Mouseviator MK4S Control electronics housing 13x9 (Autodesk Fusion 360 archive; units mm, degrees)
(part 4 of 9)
sketch "Sketch3" plane through (0, 61.9879, 0) normal (0, 1, 0) x axis (-1, 0, 0)
  line L1 (-11.0351, 5.05) -> (-100.8937, 5.05)
  line L2 (-11.0351, 74.95) -> (-11.0351, 5.05)
  line L3 (-100.8937, 74.95) -> (-11.0351, 74.95)
  line L4 (-100.8937, 5.05) -> (-100.8937, 74.95)
  line L5 (-55.9644, -6.6527) -> (-55.9644, 156.5527)
  line L6 (83.5909, 40) -> (-105.6612, 40)
  line L7 (-100.8937, 64.95) -> (-100.8937, 74.95)
  line L8 (-94.8937, 74.95) -> (-100.8937, 74.95)
  line L9 (-94.8937, 59.95) -> (-94.8937, 74.95)
  line L10 (-100.8937, 64.95) -> (-94.8937, 59.95)
  line L11 (-100.9437, 64.9735) -> (-106.8437, 60)
  line L12 (-106.8437, 60) -> (-106.8437, 74.9)
  line L13 (-100.8937, 64.9735) -> (-100.9437, 64.9735)
  line L14 (-100.8937, 74.9) -> (-106.8437, 74.9)
  line L15 (-100.8937, 5.1) -> (-106.8437, 5.1)
  line L16 (-106.8437, 20) -> (-106.8437, 5.1)
  line L17 (-100.9437, 15.0265) -> (-106.8437, 20)
  line L18 (-100.8937, 15.0265) -> (-100.9437, 15.0265)
  line L19 (-100.8937, 15.05) -> (-100.8937, 5.05)
  line L20 (-94.8937, 5.05) -> (-100.8937, 5.05)
  line L21 (-94.8937, 20.05) -> (-94.8937, 5.05)
  line L22 (-100.8937, 15.05) -> (-94.8937, 20.05)
  line L23 (-11.0351, 5.1) -> (-5.0851, 5.1)
  line L24 (-5.0851, 20) -> (-5.0851, 5.1)
  line L25 (-10.9851, 15.0265) -> (-5.0851, 20)
  line L26 (-11.0351, 15.0265) -> (-10.9851, 15.0265)
  line L27 (-11.0351, 15.05) -> (-11.0351, 5.05)
  line L28 (-17.0351, 5.05) -> (-11.0351, 5.05)
  line L29 (-17.0351, 20.05) -> (-17.0351, 5.05)
  line L30 (-11.0351, 15.05) -> (-17.0351, 20.05)
  line L31 (-11.0351, 74.9) -> (-5.0851, 74.9)
  line L32 (-5.0851, 60) -> (-5.0851, 74.9)
  line L33 (-11.0351, 64.9735) -> (-10.9851, 64.9735)
  line L34 (-10.9851, 64.9735) -> (-5.0851, 60)
  line L35 (-11.0351, 64.95) -> (-11.0351, 74.95)
  line L36 (-17.0351, 74.95) -> (-11.0351, 74.95)
  line L37 (-17.0351, 59.95) -> (-17.0351, 74.95)
  line L38 (-11.0351, 64.95) -> (-17.0351, 59.95)
  point P17 (-100.8937, 64.9735)
  point P18 (-100.8937, 74.9)
  point P10 (-100.8937, 74.95)
  point P24 (-100.8937, 5.05)
  point P11 (-100.8937, 64.95)
  point P25 (-100.8937, 15.05)
  point P12 (-94.8937, 74.95)
  point P26 (-94.8937, 5.05)
  point P13 (-94.8937, 59.95)
  point P27 (-94.8937, 20.05)
  point P14 (-100.9437, 64.9735)
  point P22 (-100.9437, 15.0265)
  point P15 (-106.8437, 60)
  point P21 (-106.8437, 20)
  point P16 (-106.8437, 74.9)
  point P19 (-106.8437, 5.1)
  point P23 (-100.8937, 15.0265)
  point P20 (-100.8937, 5.1)
  point P42 (-11.0351, 74.95)
  point P43 (-11.0351, 64.95)
  point P44 (-17.0351, 74.95)
  point P45 (-17.0351, 59.95)
  point P40 (-10.9851, 64.9735)
  point P39 (-5.0851, 60)
  point P37 (-5.0851, 74.9)
  point P41 (-11.0351, 64.9735)
  point P38 (-11.0351, 74.9)
  point P28 (-5.0851, 5.1)
  point P29 (-11.0351, 5.1)
  point P30 (-5.0851, 20)
  point P31 (-10.9851, 15.0265)
  point P32 (-11.0351, 15.0265)
  point P33 (-11.0351, 5.05)
  point P34 (-11.0351, 15.05)
  point P35 (-17.0351, 5.05)
  point P36 (-17.0351, 20.05)
  vertical L5
  horizontal L6
  midpoint L3 L5
  midpoint L2 L6
  coincident L7 P17
  coincident L4 P17
  perpendicular L7 L14
  coincident L4 P18
  symmetric L6 P10 P24
  symmetric L6 P11 P25
  symmetric L6 P12 P26
  symmetric L6 P13 P27
  symmetric L6 P14 P22
  symmetric L6 P15 P21
  symmetric L6 P16 P19
  symmetric L6 P17 P23
  symmetric L6 P18 P20
  symmetric L5 P10 P42
  symmetric L5 P11 P43
  symmetric L5 P12 P44
  symmetric L5 P13 P45
  symmetric L5 P14 P40
  symmetric L5 P15 P39
  symmetric L5 P16 P37
  symmetric L5 P17 P41
  symmetric L5 P18 P38
  symmetric L5 P19 P28
  symmetric L5 P20 P29
  symmetric L5 P21 P30
  symmetric L5 P22 P31
  symmetric L5 P23 P32
  symmetric L5 P24 P33
  symmetric L5 P25 P34
  symmetric L5 P26 P35
  symmetric L5 P27 P36
  dimension "d332_1" distance P12 P13 = 15 (= "join_width2")
  dimension "d333_1" distance P10 P12 = 6 (= "join_depth * 2")
  dimension "d334_1" distance P10 P11 = 10 (= "join_width1")
  dimension "d336_1" distance P15 P16 = 14.9 (= "join_width2 - ( 2 * wall_clearance )")
  dimension "d337_1" distance P16 P18 = 5.95 (= "join_depth * 2 - wall_clearance")
  dimension "d338_1" distance P14 P17 = 0.05 (= "wall_clearance")
sketch "Sketch1" plane through (0, 0, 5) normal (0, 0, 1) x axis (-1, 0, 0)
  line L1 (-98.9644, -53.9879) -> (-98.9644, -59.9879)
  line L2 (-92.9644, -53.9879) -> (-98.9644, -53.9879)
  line L3 (-92.9644, -59.9879) -> (-92.9644, -53.9879)
  line L4 (-98.9644, -59.9879) -> (-92.9644, -59.9879)
  line L5 (-12.9644, 60.0121) -> (-12.9644, 66.0121)
  line L6 (-18.9644, 60.0121) -> (-12.9644, 60.0121)
  line L7 (-18.9644, 66.0121) -> (-18.9644, 60.0121)
  line L8 (-12.9644, 66.0121) -> (-18.9644, 66.0121)
  line L9 (-45.9644, -51.9879) -> (-20.9644, -51.9879)
  line L10 (-40.9644, -54.9879) -> (-45.9644, -51.9879)
  line L11 (-70.9644, -54.9879) -> (-40.9644, -54.9879)
  line L12 (-65.9644, -51.9879) -> (-70.9644, -54.9879)
  line L13 (-90.9644, -51.9879) -> (-65.9644, -51.9879)
  line L14 (-90.9644, -6.9879) -> (-90.9644, -51.9879)
  line L15 (-93.9644, -11.9879) -> (-90.9644, -6.9879)
  line L16 (-93.9644, 18.0121) -> (-93.9644, -11.9879)
  line L17 (-90.9644, 13.0121) -> (-93.9644, 18.0121)
  line L18 (-90.9644, 58.0121) -> (-90.9644, 13.0121)
  line L19 (-65.9644, 58.0121) -> (-90.9644, 58.0121)
  line L20 (-70.9644, 61.0121) -> (-65.9644, 58.0121)
  line L21 (-40.9644, 61.0121) -> (-70.9644, 61.0121)
  line L22 (-45.9644, 58.0121) -> (-40.9644, 61.0121)
  line L23 (-20.9644, 58.0121) -> (-45.9644, 58.0121)
  line L24 (-20.9644, 13.0121) -> (-20.9644, 58.0121)
  line L25 (-17.9644, 18.0121) -> (-20.9644, 13.0121)
  line L26 (-17.9644, -11.9879) -> (-17.9644, 18.0121)
  line L27 (-20.9644, -6.9879) -> (-17.9644, -11.9879)
  line L28 (-20.9644, -51.9879) -> (-20.9644, -6.9879)
  line L29 (-12.9644, -53.9879) -> (-18.9644, -53.9879)
  line L30 (-12.9644, -59.9879) -> (-12.9644, -53.9879)
  line L31 (-18.9644, -59.9879) -> (-12.9644, -59.9879)
  line L32 (-18.9644, -53.9879) -> (-18.9644, -59.9879)
  line L33 (-98.9644, 60.0121) -> (-92.9644, 60.0121)
  line L34 (-98.9644, 66.0121) -> (-98.9644, 60.0121)
  line L35 (-92.9644, 66.0121) -> (-98.9644, 66.0121)
  line L36 (-92.9644, 60.0121) -> (-92.9644, 66.0121)
  line L37 (-10.9644, -6.9879) -> (-10.9644, -61.9879)
  line L38 (-13.9644, -11.9879) -> (-10.9644, -6.9879)
  line L39 (-13.9644, 18.0121) -> (-13.9644, -11.9879)
  line L40 (-10.9644, 13.0121) -> (-13.9644, 18.0121)
  line L41 (-10.9644, 68.0121) -> (-10.9644, 13.0121)
  line L42 (-45.9644, 68.0121) -> (-10.9644, 68.0121)
  line L43 (-40.9644, 65.0121) -> (-45.9644, 68.0121)
  line L44 (-70.9644, 65.0121) -> (-40.9644, 65.0121)
  line L45 (-65.9644, 68.0121) -> (-70.9644, 65.0121)
  line L46 (-100.9644, 68.0121) -> (-65.9644, 68.0121)
  line L47 (-100.9644, 13.0121) -> (-100.9644, 68.0121)
  line L48 (-97.9644, 18.0121) -> (-100.9644, 13.0121)
  line L49 (-97.9644, -11.9879) -> (-97.9644, 18.0121)
  line L50 (-100.9644, -6.9879) -> (-97.9644, -11.9879)
  line L51 (-100.9644, -61.9879) -> (-100.9644, -6.9879)
  line L52 (-65.9644, -61.9879) -> (-100.9644, -61.9879)
  line L53 (-70.9644, -58.9879) -> (-65.9644, -61.9879)
  line L54 (-40.9644, -58.9879) -> (-70.9644, -58.9879)
  line L55 (-45.9644, -61.9879) -> (-40.9644, -58.9879)
  line L56 (-10.9644, -61.9879) -> (-45.9644, -61.9879)
  line L57 (-100.9644, -61.9879) -> (-10.9644, -61.9879)
  line L58 (-99.9644, -60.9879) -> (-100.9644, -61.9879)
  line L59 (-91.9644, -60.9879) -> (-99.9644, -60.9879)
  line L60 (-91.9644, -59.9879) -> (-91.9644, -60.9879)
  line L61 (-19.9644, -59.9879) -> (-91.9644, -59.9879)
  line L62 (-19.9644, -60.9879) -> (-19.9644, -59.9879)
  line L63 (-11.9644, -60.9879) -> (-19.9644, -60.9879)
  line L64 (-10.9644, -61.9879) -> (-11.9644, -60.9879)
  line L65 (-99.9437, -61.0379) -> (-100.8937, -61.9879)
  line L66 (-91.9144, -61.0379) -> (-99.9437, -61.0379)
  line L67 (-91.9144, -60.0379) -> (-91.9144, -61.0379)
  line L68 (-20.0144, -60.0379) -> (-91.9144, -60.0379)
  line L69 (-20.0144, -61.0379) -> (-20.0144, -60.0379)
  line L70 (-11.9851, -61.0379) -> (-20.0144, -61.0379)
  line L71 (-11.0351, -61.9879) -> (-11.9851, -61.0379)
  circle C1 centre (-24.4644, 61.5121) radius 1.7
  circle C2 centre (-93.9644, 54.5121) radius 1.7
  circle C3 centre (-87.4644, -55.4879) radius 1.7
  circle C4 centre (-17.4644, -48.4879) radius 1.7
  circle C5 centre (-24.4644, -55.4879) radius 1.7
  circle C6 centre (-93.9644, -48.4879) radius 1.7
  circle C7 centre (-87.4644, 61.5121) radius 1.7
  circle C8 centre (-17.4644, 54.5121) radius 1.7
  point P46 (-10.9644, -61.9879)
  point P74 (-10.9644, -61.9879)
  point P61 (-100.9644, -61.9879)
  point P76 (-100.9644, -61.9879)
  point P68 (-99.9644, -60.9879)
  point P77 (-99.9644, -60.9879)
  point P69 (-91.9644, -60.9879)
  point P78 (-91.9644, -60.9879)
  point P70 (-91.9644, -59.9879)
  point P79 (-91.9644, -59.9879)
  point P71 (-19.9644, -59.9879)
  point P80 (-19.9644, -59.9879)
  point P72 (-19.9644, -60.9879)
  point P81 (-19.9644, -60.9879)
  point P73 (-11.9644, -60.9879)
  point P82 (-11.9644, -60.9879)
  point P89 (-11.0351, -61.9879)
  point P90 (-100.8937, -61.9879)
  point P75 (-100.9644, -61.9879)
  coincident P46 P74
  coincident P61 P76
  coincident P68 P77
  coincident P69 P78
  coincident P70 P79
  coincident P71 P80
  coincident P72 P81
  coincident P73 P82
  coincident L56 P89
  coincident L52 P90
  dimension "d228_2" distance L57 L70 = 0.95 (= "side_wall_thick1")
  dimension "d229_2" distance L57 L68 = 1.95 (= "side_wall_thick2")
  dimension "d230_2" distance L57 L66 = 0.95 (= "side_wall_thick1")
  dimension "d231_2" distance P74 P75 = 90 (= "plate_height")
  dimension "d232_2" distance L64 L71 = 0.05 (= "wall_clearance")
  dimension "d233_2" distance L58 L65 = 0.05 (= "wall_clearance")
  dimension "d234_2" angle L57 L58 = 45 (= "wall_rorner_angle")
  dimension "d235_2" distance P74 L69 = 9.05 (= "side_wall_col_length")
  dimension "d244_2" distance P75 L67 = 9.05 (= "side_wall_col_length")
extrude "Extrude1" new body sketch "Sketch1" profile of L52 L53 L55 L56 blind 69.9 (= "column_height - ( 2 * wall_clearance )") named "d217_2" from offset 0.05 (= "wall_clearance") named "d216_2"
sketch "Sketch2" plane through (0, 61.9879, 0) normal (0, 1, 0) x axis (-1, 0, 0)
  line L1 (-11.0351, 74.95) -> (-100.8937, 74.95)
  line L2 (-100.8937, 74.95) -> (-100.8937, 5.05)
  line L3 (-11.0351, 74.95) -> (-11.0351, 5.05)
  line L4 (-11.0351, 5.05) -> (-100.8937, 5.05)
  line L5 (-11.0351, 74.95) -> (-11.0351, 5.05)
  line L6 (-100.8937, 74.95) -> (-11.0351, 74.95)
  line L7 (-100.8937, 5.05) -> (-100.8937, 74.95)
  line L8 (-90.8937, 64.95) -> (-21.0351, 64.95)
  line L9 (-90.8937, 15.05) -> (-90.8937, 64.95)
  line L10 (-21.0351, 15.05) -> (-90.8937, 15.05)
  line L11 (-21.0351, 64.95) -> (-21.0351, 15.05)
  circle C1 centre (-95.9644, 60) radius 1.7
  circle C2 centre (-95.9644, 20) radius 1.7
  circle C3 centre (-15.9644, 20) radius 1.7
  circle C4 centre (-15.9644, 60) radius 1.7
hole "Hole1" HoleDepth 4 named "d220_2" HoleDiameter 3.4 named "d221_2" TipAngle 118 named "d222_2"
sketch "Sketch3" plane through (0, 61.9879, 0) normal (0, 1, 0) x axis (-1, 0, 0)
  line L1 (-11.0351, 5.05) -> (-100.8937, 5.05)
  line L2 (-11.0351, 74.95) -> (-11.0351, 5.05)
  line L3 (-100.8937, 74.95) -> (-11.0351, 74.95)
  line L4 (-100.8937, 5.05) -> (-100.8937, 74.95)
  line L5 (-55.9644, -6.6527) -> (-55.9644, 156.5527)
  line L6 (83.5909, 40) -> (-105.6612, 40)
  line L7 (-100.8937, 64.95) -> (-100.8937, 74.95)
  line L8 (-94.8937, 74.95) -> (-100.8937, 74.95)
  line L9 (-94.8937, 59.95) -> (-94.8937, 74.95)
  line L10 (-100.8937, 64.95) -> (-94.8937, 59.95)
  line L11 (-100.9437, 64.9735) -> (-106.8437, 60)
  line L12 (-106.8437, 60) -> (-106.8437, 74.9)
  line L13 (-100.8937, 64.9735) -> (-100.9437, 64.9735)
  line L14 (-100.8937, 74.9) -> (-106.8437, 74.9)
  line L15 (-100.8937, 5.1) -> (-106.8437, 5.1)
  line L16 (-106.8437, 20) -> (-106.8437, 5.1)
  line L17 (-100.9437, 15.0265) -> (-106.8437, 20)
  line L18 (-100.8937, 15.0265) -> (-100.9437, 15.0265)
  line L19 (-100.8937, 15.05) -> (-100.8937, 5.05)
  line L20 (-94.8937, 5.05) -> (-100.8937, 5.05)
  line L21 (-94.8937, 20.05) -> (-94.8937, 5.05)
  line L22 (-100.8937, 15.05) -> (-94.8937, 20.05)
  line L23 (-11.0351, 5.1) -> (-5.0851, 5.1)
  line L24 (-5.0851, 20) -> (-5.0851, 5.1)
  line L25 (-10.9851, 15.0265) -> (-5.0851, 20)
  line L26 (-11.0351, 15.0265) -> (-10.9851, 15.0265)
  line L27 (-11.0351, 15.05) -> (-11.0351, 5.05)
  line L28 (-17.0351, 5.05) -> (-11.0351, 5.05)
  line L29 (-17.0351, 20.05) -> (-17.0351, 5.05)
  line L30 (-11.0351, 15.05) -> (-17.0351, 20.05)
  line L31 (-11.0351, 74.9) -> (-5.0851, 74.9)
  line L32 (-5.0851, 60) -> (-5.0851, 74.9)
  line L33 (-11.0351, 64.9735) -> (-10.9851, 64.9735)
  line L34 (-10.9851, 64.9735) -> (-5.0851, 60)
  line L35 (-11.0351, 64.95) -> (-11.0351, 74.95)
  line L36 (-17.0351, 74.95) -> (-11.0351, 74.95)
  line L37 (-17.0351, 59.95) -> (-17.0351, 74.95)
  line L38 (-11.0351, 64.95) -> (-17.0351, 59.95)
  point P17 (-100.8937, 64.9735)
  point P18 (-100.8937, 74.9)
  point P10 (-100.8937, 74.95)
  point P24 (-100.8937, 5.05)
  point P11 (-100.8937, 64.95)
  point P25 (-100.8937, 15.05)
  point P12 (-94.8937, 74.95)
  point P26 (-94.8937, 5.05)
  point P13 (-94.8937, 59.95)
  point P27 (-94.8937, 20.05)
  point P14 (-100.9437, 64.9735)
  point P22 (-100.9437, 15.0265)
  point P15 (-106.8437, 60)
  point P21 (-106.8437, 20)
  point P16 (-106.8437, 74.9)
  point P19 (-106.8437, 5.1)
  point P23 (-100.8937, 15.0265)
  point P20 (-100.8937, 5.1)
  point P42 (-11.0351, 74.95)
  point P43 (-11.0351, 64.95)
  point P44 (-17.0351, 74.95)
  point P45 (-17.0351, 59.95)
  point P40 (-10.9851, 64.9735)
  point P39 (-5.0851, 60)
  point P37 (-5.0851, 74.9)
  point P41 (-11.0351, 64.9735)
  point P38 (-11.0351, 74.9)
  point P28 (-5.0851, 5.1)
  point P29 (-11.0351, 5.1)
  point P30 (-5.0851, 20)
  point P31 (-10.9851, 15.0265)
  point P32 (-11.0351, 15.0265)
  point P33 (-11.0351, 5.05)
  point P34 (-11.0351, 15.05)
  point P35 (-17.0351, 5.05)
  point P36 (-17.0351, 20.05)
  vertical L5
  horizontal L6
  midpoint L3 L5
  midpoint L2 L6
  coincident L7 P17
  coincident L4 P17
  perpendicular L7 L14
  coincident L4 P18
  symmetric L6 P10 P24
  symmetric L6 P11 P25
  symmetric L6 P12 P26
  symmetric L6 P13 P27
  symmetric L6 P14 P22
  symmetric L6 P15 P21
  symmetric L6 P16 P19
  symmetric L6 P17 P23
  symmetric L6 P18 P20
  symmetric L5 P10 P42
  symmetric L5 P11 P43
  symmetric L5 P12 P44
  symmetric L5 P13 P45
  symmetric L5 P14 P40
  symmetric L5 P15 P39
  symmetric L5 P16 P37
  symmetric L5 P17 P41
  symmetric L5 P18 P38
  symmetric L5 P19 P28
  symmetric L5 P20 P29
  symmetric L5 P21 P30
  symmetric L5 P22 P31
  symmetric L5 P23 P32
  symmetric L5 P24 P33
  symmetric L5 P25 P34
  symmetric L5 P26 P35
  symmetric L5 P27 P36
  dimension "d332_2" distance P12 P13 = 15 (= "join_width2")
  dimension "d333_2" distance P10 P12 = 6 (= "join_depth * 2")
  dimension "d334_2" distance P10 P11 = 10 (= "join_width1")
  dimension "d336_2" distance P15 P16 = 14.9 (= "join_width2 - ( 2 * wall_clearance )")
  dimension "d337_2" distance P16 P18 = 5.95 (= "join_depth * 2 - wall_clearance")
  dimension "d338_2" distance P14 P17 = 0.05 (= "wall_clearance")
sketch "Sketch1" plane through (0, 0, 5) normal (0, 0, 1) x axis (-1, 0, 0)
  line L1 (-98.9644, -53.9879) -> (-98.9644, -59.9879)
  line L2 (-92.9644, -53.9879) -> (-98.9644, -53.9879)
  line L3 (-92.9644, -59.9879) -> (-92.9644, -53.9879)
  line L4 (-98.9644, -59.9879) -> (-92.9644, -59.9879)
  line L5 (-12.9644, 60.0121) -> (-12.9644, 66.0121)
  line L6 (-18.9644, 60.0121) -> (-12.9644, 60.0121)
  line L7 (-18.9644, 66.0121) -> (-18.9644, 60.0121)
  line L8 (-12.9644, 66.0121) -> (-18.9644, 66.0121)
  line L9 (-45.9644, -51.9879) -> (-20.9644, -51.9879)
  line L10 (-40.9644, -54.9879) -> (-45.9644, -51.9879)
  line L11 (-70.9644, -54.9879) -> (-40.9644, -54.9879)
  line L12 (-65.9644, -51.9879) -> (-70.9644, -54.9879)
  line L13 (-90.9644, -51.9879) -> (-65.9644, -51.9879)
  line L14 (-90.9644, -6.9879) -> (-90.9644, -51.9879)
  line L15 (-93.9644, -11.9879) -> (-90.9644, -6.9879)
  line L16 (-93.9644, 18.0121) -> (-93.9644, -11.9879)
  line L17 (-90.9644, 13.0121) -> (-93.9644, 18.0121)
  line L18 (-90.9644, 58.0121) -> (-90.9644, 13.0121)
  line L19 (-65.9644, 58.0121) -> (-90.9644, 58.0121)
  line L20 (-70.9644, 61.0121) -> (-65.9644, 58.0121)
  line L21 (-40.9644, 61.0121) -> (-70.9644, 61.0121)
  line L22 (-45.9644, 58.0121) -> (-40.9644, 61.0121)
  line L23 (-20.9644, 58.0121) -> (-45.9644, 58.0121)
  line L24 (-20.9644, 13.0121) -> (-20.9644, 58.0121)
  line L25 (-17.9644, 18.0121) -> (-20.9644, 13.0121)
  line L26 (-17.9644, -11.9879) -> (-17.9644, 18.0121)
  line L27 (-20.9644, -6.9879) -> (-17.9644, -11.9879)
  line L28 (-20.9644, -51.9879) -> (-20.9644, -6.9879)
  line L29 (-12.9644, -53.9879) -> (-18.9644, -53.9879)
  line L30 (-12.9644, -59.9879) -> (-12.9644, -53.9879)
  line L31 (-18.9644, -59.9879) -> (-12.9644, -59.9879)
  line L32 (-18.9644, -53.9879) -> (-18.9644, -59.9879)
  line L33 (-98.9644, 60.0121) -> (-92.9644, 60.0121)
  line L34 (-98.9644, 66.0121) -> (-98.9644, 60.0121)
  line L35 (-92.9644, 66.0121) -> (-98.9644, 66.0121)
  line L36 (-92.9644, 60.0121) -> (-92.9644, 66.0121)
  line L37 (-10.9644, -6.9879) -> (-10.9644, -61.9879)
  line L38 (-13.9644, -11.9879) -> (-10.9644, -6.9879)
  line L39 (-13.9644, 18.0121) -> (-13.9644, -11.9879)
  line L40 (-10.9644, 13.0121) -> (-13.9644, 18.0121)
  line L41 (-10.9644, 68.0121) -> (-10.9644, 13.0121)
  line L42 (-45.9644, 68.0121) -> (-10.9644, 68.0121)
  line L43 (-40.9644, 65.0121) -> (-45.9644, 68.0121)
  line L44 (-70.9644, 65.0121) -> (-40.9644, 65.0121)
  line L45 (-65.9644, 68.0121) -> (-70.9644, 65.0121)
  line L46 (-100.9644, 68.0121) -> (-65.9644, 68.0121)
  line L47 (-100.9644, 13.0121) -> (-100.9644, 68.0121)
  line L48 (-97.9644, 18.0121) -> (-100.9644, 13.0121)
  line L49 (-97.9644, -11.9879) -> (-97.9644, 18.0121)
  line L50 (-100.9644, -6.9879) -> (-97.9644, -11.9879)
  line L51 (-100.9644, -61.9879) -> (-100.9644, -6.9879)
  line L52 (-65.9644, -61.9879) -> (-100.9644, -61.9879)
  line L53 (-70.9644, -58.9879) -> (-65.9644, -61.9879)
  line L54 (-40.9644, -58.9879) -> (-70.9644, -58.9879)
  line L55 (-45.9644, -61.9879) -> (-40.9644, -58.9879)
  line L56 (-10.9644, -61.9879) -> (-45.9644, -61.9879)
  line L57 (-100.9644, -61.9879) -> (-10.9644, -61.9879)
  line L58 (-99.9644, -60.9879) -> (-100.9644, -61.9879)
  line L59 (-91.9644, -60.9879) -> (-99.9644, -60.9879)
  line L60 (-91.9644, -59.9879) -> (-91.9644, -60.9879)
  line L61 (-19.9644, -59.9879) -> (-91.9644, -59.9879)
  line L62 (-19.9644, -60.9879) -> (-19.9644, -59.9879)
  line L63 (-11.9644, -60.9879) -> (-19.9644, -60.9879)
  line L64 (-10.9644, -61.9879) -> (-11.9644, -60.9879)
  line L65 (-99.9437, -61.0379) -> (-100.8937, -61.9879)
  line L66 (-91.9144, -61.0379) -> (-99.9437, -61.0379)
  line L67 (-91.9144, -60.0379) -> (-91.9144, -61.0379)
  line L68 (-20.0144, -60.0379) -> (-91.9144, -60.0379)
  line L69 (-20.0144, -61.0379) -> (-20.0144, -60.0379)
  line L70 (-11.9851, -61.0379) -> (-20.0144, -61.0379)
  line L71 (-11.0351, -61.9879) -> (-11.9851, -61.0379)
  circle C1 centre (-24.4644, 61.5121) radius 1.7
  circle C2 centre (-93.9644, 54.5121) radius 1.7
  circle C3 centre (-87.4644, -55.4879) radius 1.7
  circle C4 centre (-17.4644, -48.4879) radius 1.7
  circle C5 centre (-24.4644, -55.4879) radius 1.7
  circle C6 centre (-93.9644, -48.4879) radius 1.7
  circle C7 centre (-87.4644, 61.5121) radius 1.7
  circle C8 centre (-17.4644, 54.5121) radius 1.7
  point P46 (-10.9644, -61.9879)
  point P74 (-10.9644, -61.9879)
  point P61 (-100.9644, -61.9879)
  point P76 (-100.9644, -61.9879)
  point P68 (-99.9644, -60.9879)
  point P77 (-99.9644, -60.9879)
  point P69 (-91.9644, -60.9879)
  point P78 (-91.9644, -60.9879)
  point P70 (-91.9644, -59.9879)
  point P79 (-91.9644, -59.9879)
  point P71 (-19.9644, -59.9879)
  point P80 (-19.9644, -59.9879)
  point P72 (-19.9644, -60.9879)
  point P81 (-19.9644, -60.9879)
  point P73 (-11.9644, -60.9879)
  point P82 (-11.9644, -60.9879)
  point P89 (-11.0351, -61.9879)
  point P90 (-100.8937, -61.9879)
  point P75 (-100.9644, -61.9879)
  coincident P46 P74
  coincident P61 P76
  coincident P68 P77
  coincident P69 P78
  coincident P70 P79
  coincident P71 P80
  coincident P72 P81
  coincident P73 P82
  coincident L56 P89
  coincident L52 P90
  dimension "d228_3" distance L57 L70 = 0.95 (= "side_wall_thick1")
  dimension "d229_3" distance L57 L68 = 1.95 (= "side_wall_thick2")
  dimension "d230_3" distance L57 L66 = 0.95 (= "side_wall_thick1")
  dimension "d231_3" distance P74 P75 = 90 (= "plate_height")
  dimension "d232_3" distance L64 L71 = 0.05 (= "wall_clearance")
  dimension "d233_3" distance L58 L65 = 0.05 (= "wall_clearance")
  dimension "d234_3" angle L57 L58 = 45 (= "wall_rorner_angle")
  dimension "d235_3" distance P74 L69 = 9.05 (= "side_wall_col_length")
  dimension "d244_3" distance P75 L67 = 9.05 (= "side_wall_col_length")
extrude "Extrude1" new body sketch "Sketch1" profile of L52 L53 L55 L56 blind 69.9 (= "column_height - ( 2 * wall_clearance )") named "d217_3" from offset 0.05 (= "wall_clearance") named "d216_3"
sketch "Sketch2" plane through (0, 61.9879, 0) normal (0, 1, 0) x axis (-1, 0, 0)
  line L1 (-11.0351, 74.95) -> (-100.8937, 74.95)
  line L2 (-100.8937, 74.95) -> (-100.8937, 5.05)
  line L3 (-11.0351, 74.95) -> (-11.0351, 5.05)
  line L4 (-11.0351, 5.05) -> (-100.8937, 5.05)
  line L5 (-11.0351, 74.95) -> (-11.0351, 5.05)
  line L6 (-100.8937, 74.95) -> (-11.0351, 74.95)
  line L7 (-100.8937, 5.05) -> (-100.8937, 74.95)
  line L8 (-90.8937, 64.95) -> (-21.0351, 64.95)
  line L9 (-90.8937, 15.05) -> (-90.8937, 64.95)
  line L10 (-21.0351, 15.05) -> (-90.8937, 15.05)
  line L11 (-21.0351, 64.95) -> (-21.0351, 15.05)
  circle C1 centre (-95.9644, 60) radius 1.7
  circle C2 centre (-95.9644, 20) radius 1.7
  circle C3 centre (-15.9644, 20) radius 1.7
  circle C4 centre (-15.9644, 60) radius 1.7
hole "Hole1" HoleDepth 4 named "d220_3" HoleDiameter 3.4 named "d221_3" TipAngle 118 named "d222_3"
sketch "Sketch3" plane through (0, 61.9879, 0) normal (0, 1, 0) x axis (-1, 0, 0)
  line L1 (-11.0351, 5.05) -> (-100.8937, 5.05)
  line L2 (-11.0351, 74.95) -> (-11.0351, 5.05)
  line L3 (-100.8937, 74.95) -> (-11.0351, 74.95)
  line L4 (-100.8937, 5.05) -> (-100.8937, 74.95)
  line L5 (-55.9644, -6.6527) -> (-55.9644, 156.5527)
  line L6 (83.5909, 40) -> (-105.6612, 40)
  line L7 (-100.8937, 64.95) -> (-100.8937, 74.95)
  line L8 (-94.8937, 74.95) -> (-100.8937, 74.95)
  line L9 (-94.8937, 59.95) -> (-94.8937, 74.95)
  line L10 (-100.8937, 64.95) -> (-94.8937, 59.95)
  line L11 (-100.9437, 64.9735) -> (-106.8437, 60)
  line L12 (-106.8437, 60) -> (-106.8437, 74.9)
  line L13 (-100.8937, 64.9735) -> (-100.9437, 64.9735)
  line L14 (-100.8937, 74.9) -> (-106.8437, 74.9)
  line L15 (-100.8937, 5.1) -> (-106.8437, 5.1)
  line L16 (-106.8437, 20) -> (-106.8437, 5.1)
  line L17 (-100.9437, 15.0265) -> (-106.8437, 20)
  line L18 (-100.8937, 15.0265) -> (-100.9437, 15.0265)
  line L19 (-100.8937, 15.05) -> (-100.8937, 5.05)
  line L20 (-94.8937, 5.05) -> (-100.8937, 5.05)
  line L21 (-94.8937, 20.05) -> (-94.8937, 5.05)
  line L22 (-100.8937, 15.05) -> (-94.8937, 20.05)
  line L23 (-11.0351, 5.1) -> (-5.0851, 5.1)
  line L24 (-5.0851, 20) -> (-5.0851, 5.1)
  line L25 (-10.9851, 15.0265) -> (-5.0851, 20)
  line L26 (-11.0351, 15.0265) -> (-10.9851, 15.0265)
  line L27 (-11.0351, 15.05) -> (-11.0351, 5.05)
  line L28 (-17.0351, 5.05) -> (-11.0351, 5.05)
  line L29 (-17.0351, 20.05) -> (-17.0351, 5.05)
  line L30 (-11.0351, 15.05) -> (-17.0351, 20.05)
  line L31 (-11.0351, 74.9) -> (-5.0851, 74.9)
  line L32 (-5.0851, 60) -> (-5.0851, 74.9)
  line L33 (-11.0351, 64.9735) -> (-10.9851, 64.9735)
  line L34 (-10.9851, 64.9735) -> (-5.0851, 60)
  line L35 (-11.0351, 64.95) -> (-11.0351, 74.95)
  line L36 (-17.0351, 74.95) -> (-11.0351, 74.95)
  line L37 (-17.0351, 59.95) -> (-17.0351, 74.95)
  line L38 (-11.0351, 64.95) -> (-17.0351, 59.95)
  point P17 (-100.8937, 64.9735)
  point P18 (-100.8937, 74.9)
  point P10 (-100.8937, 74.95)
  point P24 (-100.8937, 5.05)
  point P11 (-100.8937, 64.95)
  point P25 (-100.8937, 15.05)
  point P12 (-94.8937, 74.95)
  point P26 (-94.8937, 5.05)
  point P13 (-94.8937, 59.95)
  point P27 (-94.8937, 20.05)
  point P14 (-100.9437, 64.9735)
  point P22 (-100.9437, 15.0265)
  point P15 (-106.8437, 60)
  point P21 (-106.8437, 20)
  point P16 (-106.8437, 74.9)
  point P19 (-106.8437, 5.1)
  point P23 (-100.8937, 15.0265)
  point P20 (-100.8937, 5.1)
  point P42 (-11.0351, 74.95)
  point P43 (-11.0351, 64.95)
  point P44 (-17.0351, 74.95)
  point P45 (-17.0351, 59.95)
  point P40 (-10.9851, 64.9735)
  point P39 (-5.0851, 60)
  point P37 (-5.0851, 74.9)
  point P41 (-11.0351, 64.9735)
  point P38 (-11.0351, 74.9)
  point P28 (-5.0851, 5.1)
  point P29 (-11.0351, 5.1)
  point P30 (-5.0851, 20)
  point P31 (-10.9851, 15.0265)
  point P32 (-11.0351, 15.0265)
  point P33 (-11.0351, 5.05)
  point P34 (-11.0351, 15.05)
  point P35 (-17.0351, 5.05)
  point P36 (-17.0351, 20.05)
  vertical L5
  horizontal L6
  midpoint L3 L5
  midpoint L2 L6
  coincident L7 P17
  coincident L4 P17
  perpendicular L7 L14
  coincident L4 P18
  symmetric L6 P10 P24
  symmetric L6 P11 P25
  symmetric L6 P12 P26
  symmetric L6 P13 P27
  symmetric L6 P14 P22
  symmetric L6 P15 P21
  symmetric L6 P16 P19
  symmetric L6 P17 P23
  symmetric L6 P18 P20
  symmetric L5 P10 P42
  symmetric L5 P11 P43
  symmetric L5 P12 P44
  symmetric L5 P13 P45
  symmetric L5 P14 P40
  symmetric L5 P15 P39
  symmetric L5 P16 P37
  symmetric L5 P17 P41
  symmetric L5 P18 P38
  symmetric L5 P19 P28
  symmetric L5 P20 P29
  symmetric L5 P21 P30
  symmetric L5 P22 P31
  symmetric L5 P23 P32
  symmetric L5 P24 P33
  symmetric L5 P25 P34
  symmetric L5 P26 P35
  symmetric L5 P27 P36
  dimension "d332_3" distance P12 P13 = 15 (= "join_width2")
  dimension "d333_3" distance P10 P12 = 6 (= "join_depth * 2")
  dimension "d334_3" distance P10 P11 = 10 (= "join_width1")
  dimension "d336_3" distance P15 P16 = 14.9 (= "join_width2 - ( 2 * wall_clearance )")
  dimension "d337_3" distance P16 P18 = 5.95 (= "join_depth * 2 - wall_clearance")
  dimension "d338_3" distance P14 P17 = 0.05 (= "wall_clearance")
position "Position12"
extrude "Extrude3" cut sketch "Sketch3" profile of L1 L2 L3 L4 L7 L8 L9 L10 L19 L20 L21 L22 L27 L28 L29 L30 L35 L36 L37 L38 against normal blind 2
extrude "Extrude3" cut sketch "Sketch3" profile of L1 L3 L4 L7 L8 L9 L10 L19 L20 L21 L22 against normal blind 2
extrude "Extrude3" add sketch "Sketch3" profile of L1 L3 L4 L7 L8 L9 L10 L12 L11 L13 L14 L15 L16 L17 L18 L19 L20 L21 L22 against normal blind 0.95 (magnitude of "-side_wall_thick1")
sketch "Sketch1" plane through (0, 0, 5) normal (0, 0, 1) x axis (-1, 0, 0)
  line L1 (-98.9644, -53.9879) -> (-98.9644, -59.9879)
  line L2 (-92.9644, -53.9879) -> (-98.9644, -53.9879)
  line L3 (-92.9644, -59.9879) -> (-92.9644, -53.9879)
  line L4 (-98.9644, -59.9879) -> (-92.9644, -59.9879)
  line L5 (-98.9644, 60.0121) -> (-92.9644, 60.0121)
  line L6 (-98.9644, 66.0121) -> (-98.9644, 60.0121)
  line L7 (-92.9644, 66.0121) -> (-98.9644, 66.0121)
  line L8 (-92.9644, 60.0121) -> (-92.9644, 66.0121)
  line L9 (-12.9644, 60.0121) -> (-12.9644, 66.0121)
  line L10 (-18.9644, 60.0121) -> (-12.9644, 60.0121)
  line L11 (-18.9644, 66.0121) -> (-18.9644, 60.0121)
  line L12 (-12.9644, 66.0121) -> (-18.9644, 66.0121)
  line L13 (-12.9644, -53.9879) -> (-18.9644, -53.9879)
  line L14 (-12.9644, -59.9879) -> (-12.9644, -53.9879)
  line L15 (-18.9644, -59.9879) -> (-12.9644, -59.9879)
  line L16 (-18.9644, -53.9879) -> (-18.9644, -59.9879)
  line L17 (-45.9644, -51.9879) -> (-20.9644, -51.9879)
  line L18 (-40.9644, -54.9879) -> (-45.9644, -51.9879)
  line L19 (-70.9644, -54.9879) -> (-40.9644, -54.9879)
  line L20 (-65.9644, -51.9879) -> (-70.9644, -54.9879)
  line L21 (-90.9644, -51.9879) -> (-65.9644, -51.9879)
  line L22 (-90.9644, -6.9879) -> (-90.9644, -51.9879)
  line L23 (-93.9644, -11.9879) -> (-90.9644, -6.9879)
  line L24 (-93.9644, 18.0121) -> (-93.9644, -11.9879)
  line L25 (-90.9644, 13.0121) -> (-93.9644, 18.0121)
  line L26 (-90.9644, 58.0121) -> (-90.9644, 13.0121)
  line L27 (-65.9644, 58.0121) -> (-90.9644, 58.0121)
  line L28 (-70.9644, 61.0121) -> (-65.9644, 58.0121)
  line L29 (-40.9644, 61.0121) -> (-70.9644, 61.0121)
  line L30 (-45.9644, 58.0121) -> (-40.9644, 61.0121)
  line L31 (-20.9644, 58.0121) -> (-45.9644, 58.0121)
  line L32 (-20.9644, 13.0121) -> (-20.9644, 58.0121)
  line L33 (-17.9644, 18.0121) -> (-20.9644, 13.0121)
  line L34 (-17.9644, -11.9879) -> (-17.9644, 18.0121)
  line L35 (-20.9644, -6.9879) -> (-17.9644, -11.9879)
  line L36 (-20.9644, -51.9879) -> (-20.9644, -6.9879)
  line L37 (-10.9644, -6.9879) -> (-10.9644, -61.9879)
  line L38 (-13.9644, -11.9879) -> (-10.9644, -6.9879)
  line L39 (-13.9644, 18.0121) -> (-13.9644, -11.9879)
  line L40 (-10.9644, 13.0121) -> (-13.9644, 18.0121)
  line L41 (-10.9644, 68.0121) -> (-10.9644, 13.0121)
  line L42 (-45.9644, 68.0121) -> (-10.9644, 68.0121)
  line L43 (-40.9644, 65.0121) -> (-45.9644, 68.0121)
  line L44 (-70.9644, 65.0121) -> (-40.9644, 65.0121)
  line L45 (-65.9644, 68.0121) -> (-70.9644, 65.0121)
  line L46 (-100.9644, 68.0121) -> (-65.9644, 68.0121)
  line L47 (-100.9644, 13.0121) -> (-100.9644, 68.0121)
  line L48 (-97.9644, 18.0121) -> (-100.9644, 13.0121)
  line L49 (-97.9644, -11.9879) -> (-97.9644, 18.0121)
  line L50 (-100.9644, -6.9879) -> (-97.9644, -11.9879)
  line L51 (-100.9644, -61.9879) -> (-100.9644, -6.9879)
  line L52 (-65.9644, -61.9879) -> (-100.9644, -61.9879)
  line L53 (-70.9644, -58.9879) -> (-65.9644, -61.9879)
  line L54 (-40.9644, -58.9879) -> (-70.9644, -58.9879)
  line L55 (-45.9644, -61.9879) -> (-40.9644, -58.9879)
  line L56 (-10.9644, -61.9879) -> (-45.9644, -61.9879)
  line L57 (-45.9644, -51.9879) -> (-20.9644, -51.9879)
  line L58 (-40.9644, -54.9879) -> (-55.9644, -54.9879)
  line L59 (-40.9644, -54.9879) -> (-45.9644, -51.9879)
  line L60 (-65.9644, -51.9879) -> (-70.9644, -54.9879)
  line L61 (-70.9644, -54.9879) -> (-55.9644, -54.9879)
  line L62 (-65.9644, -51.9879) -> (-90.9644, -51.9879)
  line L63 (-90.9644, -6.9879) -> (-90.9644, -51.9879)
  line L64 (-93.9644, -11.9879) -> (-93.9644, 3.0121)
  line L65 (-93.9644, -11.9879) -> (-90.9644, -6.9879)
  line L66 (-93.9644, 18.0121) -> (-90.9644, 13.0121)
  line L67 (-93.9644, 18.0121) -> (-93.9644, 3.0121)
  line L68 (-90.9644, 58.0121) -> (-90.9644, 13.0121)
  line L69 (-65.9644, 58.0121) -> (-90.9644, 58.0121)
  line L70 (-40.9644, 61.0121) -> (-45.9644, 58.0121)
  line L71 (-40.9644, 61.0121) -> (-55.9644, 61.0121)
  line L72 (-70.9644, 61.0121) -> (-55.9644, 61.0121)
  line L73 (-65.9644, 58.0121) -> (-70.9644, 61.0121)
  line L74 (-45.9644, 58.0121) -> (-20.9644, 58.0121)
  line L75 (-20.9644, 13.0121) -> (-20.9644, 58.0121)
  line L76 (-17.9644, 18.0121) -> (-17.9644, 3.0121)
  line L77 (-17.9644, -11.9879) -> (-17.9644, 3.0121)
  line L78 (-17.9644, -11.9879) -> (-20.9644, -6.9879)
  line L79 (-17.9644, 18.0121) -> (-20.9644, 13.0121)
  line L80 (-20.9644, -6.9879) -> (-20.9644, -51.9879)
  line L81 (-65.7839, -51.9379) -> (-70.7839, -54.9379)
  line L82 (-90.9144, -51.9379) -> (-65.7839, -51.9379)
  line L83 (-90.9144, -6.8074) -> (-90.9144, -51.9379)
  line L84 (-93.9144, -11.8074) -> (-90.9144, -6.8074)
  line L85 (-93.9144, 17.8316) -> (-93.9144, -11.8074)
  line L86 (-90.9144, 12.8316) -> (-93.9144, 17.8316)
  line L87 (-90.9144, 57.9621) -> (-90.9144, 12.8316)
  line L88 (-65.7839, 57.9621) -> (-90.9144, 57.9621)
  line L89 (-70.7839, 60.9621) -> (-65.7839, 57.9621)
  line L90 (-41.1449, 60.9621) -> (-70.7839, 60.9621)
  line L91 (-46.1449, 57.9621) -> (-41.1449, 60.9621)
  line L92 (-21.0144, 57.9621) -> (-46.1449, 57.9621)
  line L93 (-21.0144, 12.8316) -> (-21.0144, 57.9621)
  line L94 (-18.0144, 17.8316) -> (-21.0144, 12.8316)
  line L95 (-18.0144, -11.8074) -> (-18.0144, 17.8316)
  line L96 (-21.0144, -6.8074) -> (-18.0144, -11.8074)
  line L97 (-21.0144, -51.9379) -> (-21.0144, -6.8074)
  line L98 (-46.1449, -51.9379) -> (-21.0144, -51.9379)
  line L99 (-41.1449, -54.9379) -> (-46.1449, -51.9379)
  line L100 (-70.7839, -54.9379) -> (-41.1449, -54.9379)
  line L101 (-90.9144, 12.8316) -> (-90.9144, -6.8074)
  line L102 (-46.1449, -51.9379) -> (-65.7839, -51.9379)
  line L103 (-21.0144, 12.8316) -> (-21.0144, -6.8074)
  line L104 (-65.7839, 57.9621) -> (-46.1449, 57.9621)
  line L105 (-80.9144, -41.9379) -> (-31.0144, -41.9379)
  line L106 (-80.9144, 47.9621) -> (-80.9144, -41.9379)
  line L107 (-31.0144, 47.9621) -> (-80.9144, 47.9621)
  line L108 (-31.0144, -41.9379) -> (-31.0144, 47.9621)
  circle C1 centre (-24.4644, 61.5121) radius 1.7
  circle C2 centre (-93.9644, 54.5121) radius 1.7
  circle C3 centre (-87.4644, -55.4879) radius 1.7
  circle C4 centre (-17.4644, -48.4879) radius 1.7
  circle C5 centre (-24.4644, -55.4879) radius 1.7
  circle C6 centre (-93.9644, -48.4879) radius 1.7
  circle C7 centre (-87.4644, 61.5121) radius 1.7
  circle C8 centre (-17.4644, 54.5121) radius 1.7
  circle C9 centre (-60.9644, -53.4879) radius 0.75
  circle C10 centre (-50.9644, -53.4879) radius 0.75
  circle C11 centre (-92.4644, -1.9879) radius 0.75
  circle C12 centre (-92.4644, 8.0121) radius 0.75
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  horizontal L105
  vertical L106
  horizontal L107
  vertical L108
  dimension "d279_1" = 0.05 (= "wall_clearance")
  dimension "d289_1" distance L82 L105 = 10 (= "plate_square_thick")
  dimension "d290_1" distance L83 L106 = 10 (= "plate_square_thick")
  dimension "d291_1" distance L97 L108 = 10 (= "plate_square_thick")
  dimension "d292_1" distance L88 L107 = 10 (= "plate_square_thick")
extrude "Extrude1" new body sketch "Sketch1" along normal blind 5 (= "plate_thick") named "d293_1"
extrude "Extrude2" add sketch "Sketch1" blind -2.45 (= "-( plate_thick / 2 ) + wall_clearance") named "d296_1" from offset 5 (= "plate_thick") named "d295_1"
position "Position13"
sketch "Sketch3" plane through (0, 0, 10) normal (0, 0, 1) x axis (-1, 0, 0)
  line L1 (-46.1449, 57.9621) -> (-21.0144, 57.9621)
  line L2 (-41.1449, 60.9621) -> (-46.1449, 57.9621)
  line L3 (-70.7839, 60.9621) -> (-41.1449, 60.9621)
  line L4 (-65.7839, 57.9621) -> (-70.7839, 60.9621)
  line L5 (-90.9144, 57.9621) -> (-65.7839, 57.9621)
  line L6 (-90.9144, 12.8316) -> (-90.9144, 57.9621)
  line L7 (-93.9144, 17.8316) -> (-90.9144, 12.8316)
  line L8 (-93.9144, -11.8074) -> (-93.9144, 17.8316)
  line L9 (-90.9144, -6.8074) -> (-93.9144, -11.8074)
  line L10 (-90.9144, -51.9379) -> (-90.9144, -6.8074)
  line L11 (-65.7839, -51.9379) -> (-90.9144, -51.9379)
  line L12 (-70.7839, -54.9379) -> (-65.7839, -51.9379)
  line L13 (-41.1449, -54.9379) -> (-70.7839, -54.9379)
  line L14 (-46.1449, -51.9379) -> (-41.1449, -54.9379)
  line L15 (-21.0144, -51.9379) -> (-46.1449, -51.9379)
  line L16 (-21.0144, -6.8074) -> (-21.0144, -51.9379)
  line L17 (-18.0144, -11.8074) -> (-21.0144, -6.8074)
  line L18 (-18.0144, 17.8316) -> (-18.0144, -11.8074)
  line L19 (-21.0144, 12.8316) -> (-18.0144, 17.8316)
  line L20 (-21.0144, 57.9621) -> (-21.0144, 12.8316)
  line L21 (-31.0144, 47.9621) -> (-80.9144, 47.9621)
  line L22 (-31.0144, -41.9379) -> (-31.0144, 47.9621)
  line L23 (-80.9144, -41.9379) -> (-31.0144, -41.9379)
  line L24 (-80.9144, 47.9621) -> (-80.9144, -41.9379)
  line L25 (-89.6144, -38.9379) -> (-23.6144, -38.9379)
  line L26 (-89.6144, -2.9379) -> (-89.6144, -38.9379)
  line L27 (-23.6144, -2.9379) -> (-89.6144, -2.9379)
  line L28 (-23.6144, -38.9379) -> (-23.6144, -2.9379)
  line L29 (-166.712, 3.0121) -> (4.8831, 3.0121)
  line L30 (-89.6144, 9.9821) -> (-23.6144, 9.9821)
  line L31 (-89.6144, 45.9821) -> (-89.6144, 9.9821)
  line L32 (-23.6144, 45.9821) -> (-89.6144, 45.9821)
  line L33 (-23.6144, 9.9821) -> (-23.6144, 45.9821)
  line L34 (-80.9144, -2.9379) -> (-31.0144, -2.9379)
  line L35 (-80.9144, 9.9821) -> (-80.9144, -2.9379)
  line L36 (-31.0144, 9.9821) -> (-80.9144, 9.9821)
  line L37 (-31.0144, -2.9379) -> (-31.0144, 9.9821)
  line L38 (-90.9144, 57.9621) -> (-90.9144, 12.8316)
  circle C1 centre (-26.1144, -36.4379) radius 1.7
  circle C2 centre (-26.1144, -36.4379) radius 4.25
  circle C3 centre (-87.1144, -36.4379) radius 1.7
  circle C4 centre (-87.1144, -36.4379) radius 4.25
  circle C5 centre (-26.1144, -5.4379) radius 1.7
  circle C6 centre (-26.1144, -5.4379) radius 4.25
  circle C7 centre (-87.1144, -5.4379) radius 1.7
  circle C8 centre (-87.1144, -5.4379) radius 4.25
  circle C9 centre (-87.1144, 43.4821) radius 4.25
  circle C10 centre (-87.1144, 43.4821) radius 1.7
  circle C11 centre (-87.1144, 12.4821) radius 4.25
  circle C12 centre (-87.1144, 12.4821) radius 1.7
  circle C13 centre (-26.1144, 12.4821) radius 1.7
  circle C14 centre (-26.1144, 12.4821) radius 4.25
  circle C15 centre (-26.1144, 43.4821) radius 4.25
  circle C16 centre (-26.1144, 43.4821) radius 1.7
  point P58 (-80.9144, 9.9821)
  point P56 (-31.0144, -2.9379)
  point P30 (-23.6144, -38.9379)
  point P31 (-89.6144, -38.9379)
  point P33 (-23.6144, -2.9379)
  point P36 (-26.1144, -36.4379)
  point P49 (-23.6144, 9.9821)
  point P52 (-89.6144, 9.9821)
  point P51 (-23.6144, 45.9821)
  point P53 (-26.1144, 12.4821)
  horizontal L25
  vertical L26
  horizontal L27
  vertical L28
  horizontal L29
  midpoint L24 L29
  concentric C1 C2
  horizontal L30
  vertical L31
  horizontal L32
  vertical L33
  concentric C13 C14
  horizontal L34
  vertical L35
  horizontal L36
  vertical L37
  coincident L30 P58
  coincident L24 P58
  coincident L27 P56
  coincident L22 P56
  dimension "power_board_width" distance P30 P31 = 66
  dimension "power_board_height" distance P30 P33 = 36
  dimension "d347" distance L10 L26 = 1.3
  dimension "d348" distance L11 L25 = 13
  dimension "d349" diameter C1 = 3.4 (= "M3_d")
  dimension "d350" distance L28 P36 = 2.5
  dimension "d351" distance L25 P36 = 2.5
  dimension "d352" diameter C2 = 8.5 (= "M3_d * 2.5")
  dimension "d361" distance P49 P52 = 66
  dimension "d362" distance P49 P51 = 36 (= "power_board_height")
  dimension "d363" diameter C13 = 3.4 (= "M3_d")
  dimension "d364" distance P53 L33 = 2.5
  dimension "d365" distance P53 L30 = 2.5
  dimension "d366" diameter C14 = 8.5 (= "M3_d * 2.5")
  dimension "d409" distance L31 L38 = 1.3
  dimension "d355" R-Pattern1-uDistance = -61 (= "-power_board_width + 5 mm")
  dimension "d356" R-Pattern1-vDistance = 31 (= "power_board_height - 5 mm")
  dimension "d359" R-Pattern2-uDistance = -61 (= "-power_board_width + 5 mm")
  dimension "d360" R-Pattern2-vDistance = 31 (= "power_board_height - 5 mm")
extrude "Extrude3" add sketch "Sketch3" profile of C1 C2 C3 C4 C5 C6 C7 C8 C9 C10 C11 C12 C13 C14 C15 C16 along normal blind 5 named "el_stand_height"
extrude "Extrude4" add sketch "Sketch3" profile of L22 L24 L34 L35 L36 L37 no distance stored
sketch "Sketch4" plane through (0, 0, 15) normal (0, 0, 1) x axis (-1, 0, 0)
  circle C1 centre (-26.1144, 12.4821) radius 4.25
hole "Hole1" HoleDepth 7.5 (= "( plate_thick + el_stand_height ) * 0.75") HoleDiameter 3.4 TipAngle 118
fillet "Fillet1" radius 1.25 (= "el_stand_height * 0.25")
sketch "Sketch1" plane through (0, 0, 5) normal (0, 0, 1) x axis (-1, 0, 0)
  line L1 (-98.9644, -53.9879) -> (-98.9644, -59.9879)
  line L2 (-92.9644, -53.9879) -> (-98.9644, -53.9879)
  line L3 (-92.9644, -59.9879) -> (-92.9644, -53.9879)
  line L4 (-98.9644, -59.9879) -> (-92.9644, -59.9879)
  line L5 (-98.9644, 60.0121) -> (-92.9644, 60.0121)
  line L6 (-98.9644, 66.0121) -> (-98.9644, 60.0121)
  line L7 (-92.9644, 66.0121) -> (-98.9644, 66.0121)
  line L8 (-92.9644, 60.0121) -> (-92.9644, 66.0121)
  line L9 (-12.9644, 60.0121) -> (-12.9644, 66.0121)
  line L10 (-18.9644, 60.0121) -> (-12.9644, 60.0121)
  line L11 (-18.9644, 66.0121) -> (-18.9644, 60.0121)
  line L12 (-12.9644, 66.0121) -> (-18.9644, 66.0121)
  line L13 (-12.9644, -53.9879) -> (-18.9644, -53.9879)
  line L14 (-12.9644, -59.9879) -> (-12.9644, -53.9879)
  line L15 (-18.9644, -59.9879) -> (-12.9644, -59.9879)
  line L16 (-18.9644, -53.9879) -> (-18.9644, -59.9879)
  line L17 (-45.9644, -51.9879) -> (-20.9644, -51.9879)
  line L18 (-40.9644, -54.9879) -> (-45.9644, -51.9879)
  line L19 (-70.9644, -54.9879) -> (-40.9644, -54.9879)
  line L20 (-65.9644, -51.9879) -> (-70.9644, -54.9879)
  line L21 (-90.9644, -51.9879) -> (-65.9644, -51.9879)
  line L22 (-90.9644, -6.9879) -> (-90.9644, -51.9879)
  line L23 (-93.9644, -11.9879) -> (-90.9644, -6.9879)
  line L24 (-93.9644, 18.0121) -> (-93.9644, -11.9879)
  line L25 (-90.9644, 13.0121) -> (-93.9644, 18.0121)
  line L26 (-90.9644, 58.0121) -> (-90.9644, 13.0121)
  line L27 (-65.9644, 58.0121) -> (-90.9644, 58.0121)
  line L28 (-70.9644, 61.0121) -> (-65.9644, 58.0121)
  line L29 (-40.9644, 61.0121) -> (-70.9644, 61.0121)
  line L30 (-45.9644, 58.0121) -> (-40.9644, 61.0121)
  line L31 (-20.9644, 58.0121) -> (-45.9644, 58.0121)
  line L32 (-20.9644, 13.0121) -> (-20.9644, 58.0121)
  line L33 (-17.9644, 18.0121) -> (-20.9644, 13.0121)
  line L34 (-17.9644, -11.9879) -> (-17.9644, 18.0121)
  line L35 (-20.9644, -6.9879) -> (-17.9644, -11.9879)
  line L36 (-20.9644, -51.9879) -> (-20.9644, -6.9879)
  line L37 (-10.9644, -6.9879) -> (-10.9644, -61.9879)
  line L38 (-13.9644, -11.9879) -> (-10.9644, -6.9879)
  line L39 (-13.9644, 18.0121) -> (-13.9644, -11.9879)
  line L40 (-10.9644, 13.0121) -> (-13.9644, 18.0121)
  line L41 (-10.9644, 68.0121) -> (-10.9644, 13.0121)
  line L42 (-45.9644, 68.0121) -> (-10.9644, 68.0121)
  line L43 (-40.9644, 65.0121) -> (-45.9644, 68.0121)
  line L44 (-70.9644, 65.0121) -> (-40.9644, 65.0121)
  line L45 (-65.9644, 68.0121) -> (-70.9644, 65.0121)
  line L46 (-100.9644, 68.0121) -> (-65.9644, 68.0121)
  line L47 (-100.9644, 13.0121) -> (-100.9644, 68.0121)
  line L48 (-97.9644, 18.0121) -> (-100.9644, 13.0121)
  line L49 (-97.9644, -11.9879) -> (-97.9644, 18.0121)
  line L50 (-100.9644, -6.9879) -> (-97.9644, -11.9879)
  line L51 (-100.9644, -61.9879) -> (-100.9644, -6.9879)
  line L52 (-65.9644, -61.9879) -> (-100.9644, -61.9879)
  line L53 (-70.9644, -58.9879) -> (-65.9644, -61.9879)
  line L54 (-40.9644, -58.9879) -> (-70.9644, -58.9879)
  line L55 (-45.9644, -61.9879) -> (-40.9644, -58.9879)
  line L56 (-10.9644, -61.9879) -> (-45.9644, -61.9879)
  line L57 (-45.9644, -51.9879) -> (-20.9644, -51.9879)
  line L58 (-40.9644, -54.9879) -> (-55.9644, -54.9879)
  line L59 (-40.9644, -54.9879) -> (-45.9644, -51.9879)
  line L60 (-65.9644, -51.9879) -> (-70.9644, -54.9879)
  line L61 (-70.9644, -54.9879) -> (-55.9644, -54.9879)
  line L62 (-65.9644, -51.9879) -> (-90.9644, -51.9879)
  line L63 (-90.9644, -6.9879) -> (-90.9644, -51.9879)
  line L64 (-93.9644, -11.9879) -> (-93.9644, 3.0121)
  line L65 (-93.9644, -11.9879) -> (-90.9644, -6.9879)
  line L66 (-93.9644, 18.0121) -> (-90.9644, 13.0121)
  line L67 (-93.9644, 18.0121) -> (-93.9644, 3.0121)
  line L68 (-90.9644, 58.0121) -> (-90.9644, 13.0121)
  line L69 (-65.9644, 58.0121) -> (-90.9644, 58.0121)
  line L70 (-40.9644, 61.0121) -> (-45.9644, 58.0121)
  line L71 (-40.9644, 61.0121) -> (-55.9644, 61.0121)
  line L72 (-70.9644, 61.0121) -> (-55.9644, 61.0121)
  line L73 (-65.9644, 58.0121) -> (-70.9644, 61.0121)
  line L74 (-45.9644, 58.0121) -> (-20.9644, 58.0121)
  line L75 (-20.9644, 13.0121) -> (-20.9644, 58.0121)
  line L76 (-17.9644, 18.0121) -> (-17.9644, 3.0121)
  line L77 (-17.9644, -11.9879) -> (-17.9644, 3.0121)
  line L78 (-17.9644, -11.9879) -> (-20.9644, -6.9879)
  line L79 (-17.9644, 18.0121) -> (-20.9644, 13.0121)
  line L80 (-20.9644, -6.9879) -> (-20.9644, -51.9879)
  line L81 (-65.7839, -51.9379) -> (-70.7839, -54.9379)
  line L82 (-90.9144, -51.9379) -> (-65.7839, -51.9379)
  line L83 (-90.9144, -6.8074) -> (-90.9144, -51.9379)
  line L84 (-93.9144, -11.8074) -> (-90.9144, -6.8074)
  line L85 (-93.9144, 17.8316) -> (-93.9144, -11.8074)
  line L86 (-90.9144, 12.8316) -> (-93.9144, 17.8316)
  line L87 (-90.9144, 57.9621) -> (-90.9144, 12.8316)
  line L88 (-65.7839, 57.9621) -> (-90.9144, 57.9621)
  line L89 (-70.7839, 60.9621) -> (-65.7839, 57.9621)
  line L90 (-41.1449, 60.9621) -> (-70.7839, 60.9621)
  line L91 (-46.1449, 57.9621) -> (-41.1449, 60.9621)
  line L92 (-21.0144, 57.9621) -> (-46.1449, 57.9621)
  line L93 (-21.0144, 12.8316) -> (-21.0144, 57.9621)
  line L94 (-18.0144, 17.8316) -> (-21.0144, 12.8316)
  line L95 (-18.0144, -11.8074) -> (-18.0144, 17.8316)
  line L96 (-21.0144, -6.8074) -> (-18.0144, -11.8074)
  line L97 (-21.0144, -51.9379) -> (-21.0144, -6.8074)
  line L98 (-46.1449, -51.9379) -> (-21.0144, -51.9379)
  line L99 (-41.1449, -54.9379) -> (-46.1449, -51.9379)
  line L100 (-70.7839, -54.9379) -> (-41.1449, -54.9379)
  line L101 (-90.9144, 12.8316) -> (-90.9144, -6.8074)
  line L102 (-46.1449, -51.9379) -> (-65.7839, -51.9379)
  line L103 (-21.0144, 12.8316) -> (-21.0144, -6.8074)
  line L104 (-65.7839, 57.9621) -> (-46.1449, 57.9621)
  line L105 (-80.9144, -41.9379) -> (-31.0144, -41.9379)
  line L106 (-80.9144, 47.9621) -> (-80.9144, -41.9379)
  line L107 (-31.0144, 47.9621) -> (-80.9144, 47.9621)
  line L108 (-31.0144, -41.9379) -> (-31.0144, 47.9621)
  circle C1 centre (-24.4644, 61.5121) radius 1.7
  circle C2 centre (-93.9644, 54.5121) radius 1.7
  circle C3 centre (-87.4644, -55.4879) radius 1.7
  circle C4 centre (-17.4644, -48.4879) radius 1.7
  circle C5 centre (-24.4644, -55.4879) radius 1.7
  circle C6 centre (-93.9644, -48.4879) radius 1.7
  circle C7 centre (-87.4644, 61.5121) radius 1.7
  circle C8 centre (-17.4644, 54.5121) radius 1.7
  circle C9 centre (-60.9644, -53.4879) radius 0.75
  circle C10 centre (-50.9644, -53.4879) radius 0.75
  circle C11 centre (-92.4644, -1.9879) radius 0.75
  circle C12 centre (-92.4644, 8.0121) radius 0.75
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  horizontal L105
  vertical L106
  horizontal L107
  vertical L108
  dimension "d279_2" = 0.05 (= "wall_clearance")
  dimension "d289_2" distance L82 L105 = 10 (= "plate_square_thick")
  dimension "d290_2" distance L83 L106 = 10 (= "plate_square_thick")
  dimension "d291_2" distance L97 L108 = 10 (= "plate_square_thick")
  dimension "d292_2" distance L88 L107 = 10 (= "plate_square_thick")
extrude "Extrude1" new body sketch "Sketch1" along normal blind 5 (= "plate_thick") named "d293_2"
extrude "Extrude2" add sketch "Sketch1" blind -2.45 (= "-( plate_thick / 2 ) + wall_clearance") named "d296_2" from offset 5 (= "plate_thick") named "d295_2"
position "Position14"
